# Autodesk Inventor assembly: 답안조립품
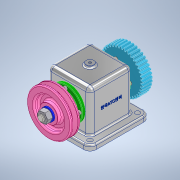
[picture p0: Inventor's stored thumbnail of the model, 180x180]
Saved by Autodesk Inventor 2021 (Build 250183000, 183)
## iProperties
Created: 2022-07
Part Number: 답안조립품
Document SubType Name: Assembly
Designer: i
Author: i
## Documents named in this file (12)
- C:\Users\i\Desktop\720706V1004\답안조립품.iam
- C:\Users\i\Desktop\720706V1004\본체.ipt
- C:\Users\i\Desktop\720706V1004\축.ipt
- C:\Users\i\Desktop\720706V1004\베어링 6204.ipt
- C:\Users\i\Desktop\720706V1004\오일실 20x35x8.ipt
- C:\Users\i\Desktop\720706V1004\커버.ipt
- C:\Users\i\Desktop\720706V1004\볼트 M4x0.7.ipt
- C:\Users\i\Desktop\720706V1004\키 5x5.ipt
- C:\Users\i\Desktop\720706V1004\V벨트풀리.ipt
- C:\Users\i\Desktop\720706V1004\너트 M12x1.25.ipt
- C:\Users\i\Desktop\720706V1004\와셔 12x24.ipt
- C:\Users\i\Desktop\720706V1004\스퍼기어.ipt
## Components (1 placed, 1 different names)
1. V벨트풀리:1
## Named parameters: d6_d1 = 0, d7_d2 = 0, d8_d3 = 0, d9_d4 = 0, d10_d5 = 0, d11_d0 = 0
